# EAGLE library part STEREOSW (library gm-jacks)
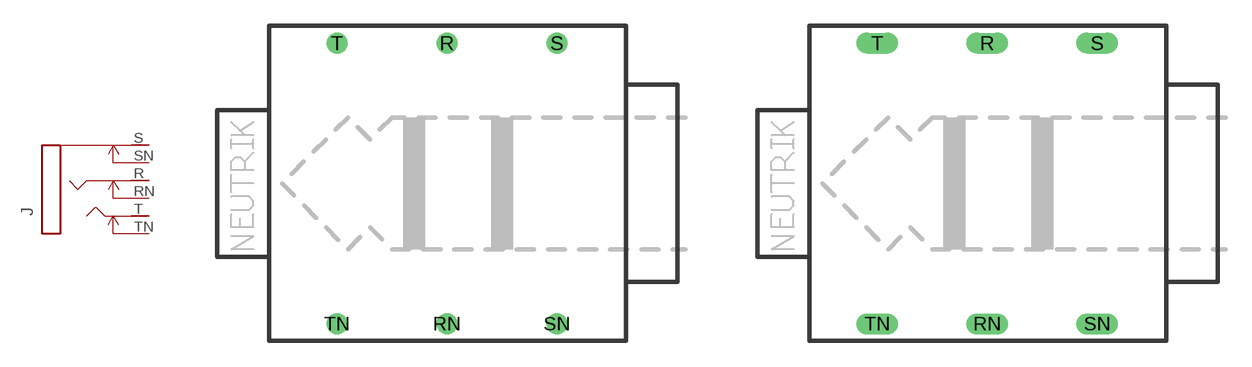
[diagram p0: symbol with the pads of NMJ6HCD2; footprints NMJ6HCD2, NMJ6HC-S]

Designator prefix J

## STEREOSW  [NMJ6HCD2]
R  R  pas
RN  RN  pas
S  S  pas
SN  SN  pas
T  T  pas
TN  TN  pas

## STEREOSWS  [NMJ6HC-S]
Pads as for NMJ6HCD2

## STEREOSWL  [NRJ6HF-1]
G  SN  pas
R  R  pas
RN  RN  pas
S  S  pas
T  T  pas
TN  TN  pas

## Footprint NMJ6HCD2 (pad centres in mm)
drill 0.7 round: R 0,8.115; RN 0,-8.115; S 6.35,8.115; SN 6.35,-8.115; T -6.35,8.115; TN -6.35,-8.115

## Footprint NMJ6HC-S (pad centres in mm)
drill 0.7 long: R 0,8.115; RN 0,-8.115; S 6.35,8.115; SN 6.35,-8.115; T -6.35,8.115; TN -6.35,-8.115

## Footprint NRJ6HF-1 (pad centres in mm)
Neutrik Slim Jack NRJ6HF-1
drill 1.5 round: G -4.2,-5.91; R 7.23,0.44; RN -4.2,0.44; S 7.23,-5.91; T 7.23,6.79; TN -4.2,6.79
hole 2 at 7.23,-2.71
hole 2 at -4.2,-2.71
hole 3 at 5.1,3.64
